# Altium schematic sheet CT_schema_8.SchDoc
size 277 x 170 mm
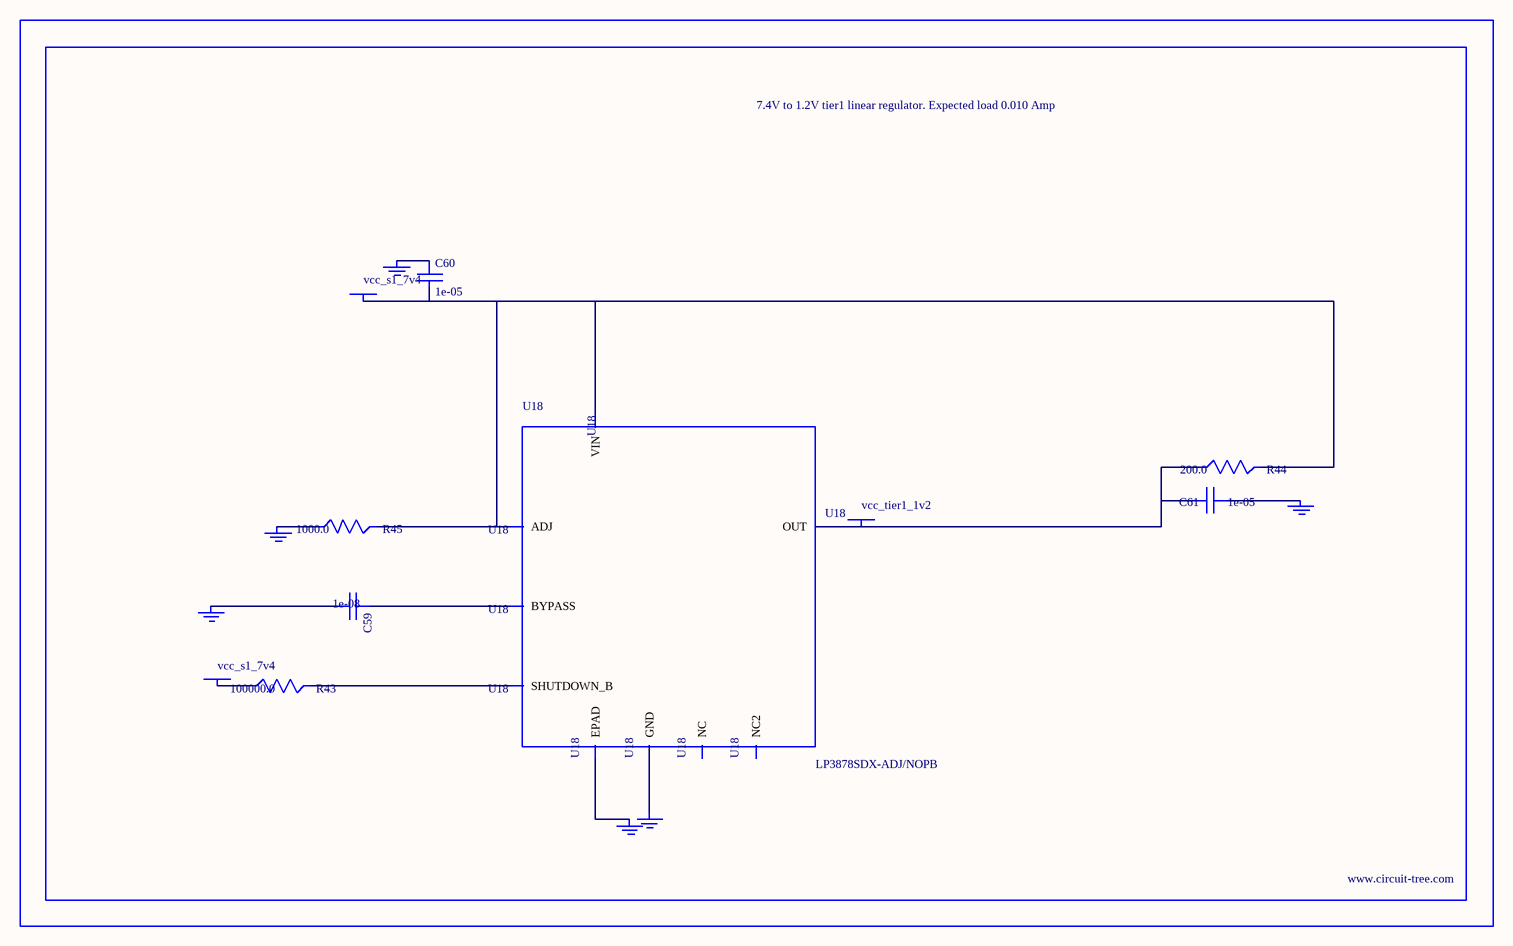
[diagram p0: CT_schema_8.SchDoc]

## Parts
BORDER7  (no value)
C59  1e-08  [C0402]
C60  1e-05  [C1206]
C61  1e-05  [C0805]
GND_INSTANCE_7_0  (no value)
GND_INSTANCE_7_1  (no value)
GND_INSTANCE_7_2  (no value)
GND_INSTANCE_7_3  (no value)
GND_INSTANCE_7_4  (no value)
GND_INSTANCE_7_5  (no value)
POWER_INSTANCE_7_0  vcc_s1_7v4
POWER_INSTANCE_7_1  vcc_s1_7v4
POWER_INSTANCE_7_2  vcc_tier1_1v2
R43  100000.0  [R0603]
R44  200.0  [R0603]
R45  1000.0  [R0603]
U18  LP3878SDX-ADJ/NOPB  [WSON-8]

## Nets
NetC59_1: C59.1 U18.1(BYPASS)
NetC59_2: C59.2 GND_INSTANCE_7_0.0(GND)
NetC60_1: C60.1 GND_INSTANCE_7_1.0(GND)
NetC60_2: C60.2 POWER_INSTANCE_7_0.0(PWR) R44.2 R45.2 U18.4(VIN) U18.6(ADJ)
NetC61_1: C61.1 GND_INSTANCE_7_2.0(GND)
NetC61_2: C61.2 POWER_INSTANCE_7_2.0(PWR) R44.1 U18.5(OUT)
NetGND_INSTANCE_7_3_0: GND_INSTANCE_7_3.0(GND) R45.1
NetGND_INSTANCE_7_4_0: GND_INSTANCE_7_4.0(GND) U18.PAD(EPAD)
NetGND_INSTANCE_7_5_0: GND_INSTANCE_7_5.0(GND) U18.3(GND)
NetPOWER_INSTANCE_7_1_0: POWER_INSTANCE_7_1.0(PWR) R43.1
NetR43_2: R43.2 U18.8(SHUTDOWN_B)

Not connected (* = marked no-connect by the designer): U18 2(NC) 7(NC2)

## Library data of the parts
BORDER7 = BORDER_PAGE7
C59 = C0402C103K3RAC
C60 = C1206C106K3RACTU
C61 = GRM219R60J106ME19D
GND_INSTANCE_7_0-GND_INSTANCE_7_5 = GND
POWER_INSTANCE_7_0-POWER_INSTANCE_7_2 = PWR
R43 = RC0603JR-07100KL
R44 = RC0603JR-07200RL
R45 = RC0603JR-071KL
